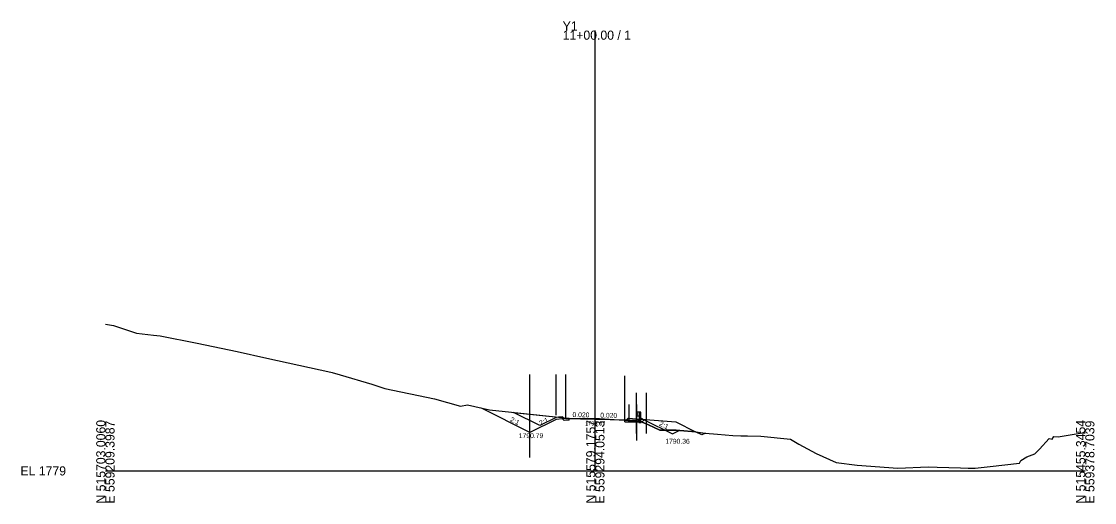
# Model space of a CAD drawing. Extents: x -26 to 303, y 990 to 1587.
# Drawn here: x -25.7 to 302.8, y 990.3 to 1137.7 of the extents above; entities that cross this region are included whole.
import ezdxf

# ---------------------------------------------------------------- set-up
doc = ezdxf.new("R2010")
doc.units = 0
for name, color, linetype in [('Exist Cross Section Cell', 7, 'Continuous'), ('Exist XS Center Line Elevation Label', 7, 'Continuous'), ('Exist XS Ground Line', 7, 'Continuous'), ('Prop XS Ditch Slope Text', 7, 'Continuous'), ('Prop XS Ditch Standard Text', 7, 'Continuous'), ('Prop XS Dump Level', 7, 'Continuous'), ('Prop XS Earthwork Shape', 7, 'Continuous'), ('Prop XS EOT Tick Mark', 7, 'Continuous'), ('Prop XS Finish Grade', 7, 'Continuous'), ('Prop XS Finish Grade Earthwork', 7, 'Continuous'), ('Prop XS Finish Grade Paved Shoulder', 7, 'Continuous'), ('Prop XS Finish Grade Pavement', 7, 'Continuous'), ('Prop XS Guardrail', 7, 'Continuous'), ('Prop XS Pvmt Edge Slope', 7, 'Continuous'), ('Prop XS SE Text', 7, 'Continuous'), ('Prop XS Side Slope Text', 7, 'Continuous'), ('Prop XS Subgrade Earthwork', 7, 'Continuous'), ('Scratch_Level_3', 7, 'Continuous'), ('Scratch_Level_6', 7, 'Continuous'), ('Typical Curb CELL', 7, 'Continuous')]:
    doc.layers.add(name, color=color, linetype=linetype)

msp = doc.modelspace()

# ---------------------------------------------------------------- linework, layer by layer
at = {"layer": 'Exist Cross Section Cell'}
for p, q in [((150, 1000), (150, 1134.87)), ((0, 1000), (150, 1000)), ((150, 1000), (300, 1000))]:
    msp.add_line(p, q, dxfattribs=at)
at = {"layer": 'Exist XS Ground Line'}
msp.add_lwpolyline([(0, 1044.96), (2.53, 1044.49), (9.5, 1042.18), (14.72, 1041.61), (16.82, 1041.37), (28.06, 1039.14), (40.38, 1036.55), (49.47, 1034.58), (69.05, 1030.26), (69.42, 1030.15), (71.85, 1029.42), (81.56, 1026.55), (85.51, 1025.2), (100.78, 1022.12), (108.77, 1019.8), (110.82, 1020.22), (117.62, 1018.66), (139.76, 1016.31), (141.98, 1016.08), (142.48, 1016.08), (150, 1016.07), (151.32, 1016.07), (157.33, 1015.64), (159.27, 1015.55), (163.39, 1015.04), (164.33, 1014.93), (166.3, 1014.11), (169.72, 1012.52), (172, 1012.5), (173.61, 1012.5), (174.74, 1012.49), (175.87, 1012.35), (180.8, 1011.97), (183.6, 1011.58), (187.44, 1011.21), (192.11, 1010.89), (194.5, 1010.73), (194.94, 1010.73), (195.79, 1010.75), (196.57, 1010.75), (200.72, 1010.63), (209.71, 1009.7), (212.32, 1008.2), (217.66, 1005.33), (223.77, 1002.53), (230.12, 1001.71), (242.62, 1000.87), (251.93, 1001.25), (254.66, 1001.1), (261.78, 1000.93), (264.17, 1000.83), (266.29, 1000.83), (270.87, 1001.32), (279.84, 1002.33), (280.32, 1003.21), (282.13, 1004.29), (284.6, 1005.28), (285.98, 1006.66), (288.94, 1009.91), (289.86, 1009.68), (290.38, 1010.49), (291.75, 1010.46), (299.07, 1011.62), (300, 1011.62)], dxfattribs=at)
msp.add_lwpolyline([(0, 1044.96), (2.53, 1044.49), (9.5, 1042.18), (14.72, 1041.61), (16.82, 1041.37), (28.06, 1039.14), (40.38, 1036.55), (49.47, 1034.58), (69.05, 1030.26), (69.42, 1030.15), (71.85, 1029.42), (81.56, 1026.55), (85.51, 1025.2), (100.78, 1022.12), (108.77, 1019.8), (110.82, 1020.22), (117.62, 1018.66), (139.76, 1016.31), (141.98, 1016.08), (142.48, 1016.08), (150, 1016.07), (151.32, 1016.07), (157.33, 1015.64), (159.27, 1015.55), (163.39, 1015.04), (164.33, 1014.93), (166.3, 1014.11), (169.72, 1012.52), (172, 1012.5), (173.61, 1012.5), (174.74, 1012.49), (175.87, 1012.35), (180.8, 1011.97), (183.6, 1011.58), (187.44, 1011.21), (192.11, 1010.89), (194.5, 1010.73), (194.94, 1010.73), (195.79, 1010.75), (196.57, 1010.75), (200.72, 1010.63), (209.71, 1009.7), (212.32, 1008.2), (217.66, 1005.33), (223.77, 1002.53), (230.12, 1001.71), (242.62, 1000.87), (251.93, 1001.25), (254.66, 1001.1), (261.78, 1000.93), (264.17, 1000.83), (266.29, 1000.83), (270.87, 1001.32), (279.84, 1002.33), (280.32, 1003.21), (282.13, 1004.29), (284.6, 1005.28), (285.98, 1006.66), (288.94, 1009.91), (289.86, 1009.68), (290.38, 1010.49), (291.75, 1010.46), (299.07, 1011.62), (300, 1011.62)], dxfattribs=at)
at = {"layer": 'Prop XS Dump Level'}
for p, q in [((141, 1016.03), (150, 1015.85)), ((150, 1015.85), (159, 1015.67))]:
    msp.add_line(p, q, dxfattribs=at)
at = {"layer": 'Prop XS Earthwork Shape'}
for points in [[(133, 1013.87), (124.98, 1017.88), (138.69, 1016.43), (138, 1016.37)], [(139.76, 1016.31), (140.24, 1016.26), (139.98, 1016.53), (138.69, 1016.43)], [(140.45, 1016.06), (140.24, 1016.26), (141.97, 1016.09)], [(159, 1015.66), (159.53, 1015.68), (160.02, 1016.17), (174.6, 1015), (180.65, 1011.98), (175.87, 1012.35), (174.74, 1012.49), (173.61, 1012.5), (172, 1012.5), (169.72, 1012.52), (166.3, 1014.11), (164.33, 1014.93), (163.39, 1015.04), (159.27, 1015.55), (159, 1015.56)], [(183.6, 1011.58), (183.73, 1011.56), (182.6, 1011), (180.65, 1011.98), (180.8, 1011.97)]]:
    msp.add_lwpolyline(points, close=True, dxfattribs=at)
at = {"layer": 'Prop XS EOT Tick Mark'}
for p, q in [((141, 1016.03), (141, 1017.03)), ((159, 1015.67), (159, 1016.67))]:
    msp.add_line(p, q, dxfattribs=at)
at = {"layer": 'Prop XS Finish Grade'}
for p, q in [((141, 1016.03), (139.97, 1015.95)), ((141, 1016.03), (139.98, 1015.95)), ((162.64, 1015.51), (164.01, 1016.17)), ((163.32, 1015.17), (164.2, 1015.14)), ((164.01, 1016.17), (165, 1015.68))]:
    msp.add_line(p, q, dxfattribs=at)
at = {"layer": 'Prop XS Finish Grade Earthwork'}
for p, q in [((130, 1011.79), (115.11, 1019.23)), ((138, 1015.79), (130, 1011.79)), ((139.97, 1015.95), (138, 1015.79)), ((165, 1015.68), (173.64, 1011.36)), ((173.64, 1011.36), (175.67, 1012.37))]:
    msp.add_line(p, q, dxfattribs=at)
at = {"layer": 'Prop XS Finish Grade Paved Shoulder'}
msp.add_line((159, 1015.67), (160.31, 1015.64), dxfattribs=at)
at = {"layer": 'Prop XS Finish Grade Pavement'}
for p, q in [((141, 1016.03), (150, 1015.85)), ((150, 1015.85), (159, 1015.67))]:
    msp.add_line(p, q, dxfattribs=at)
at = {"layer": 'Prop XS Guardrail'}
for p, q in [((162.67, 1017.77), (162.64, 1017.71)), ((162.64, 1017.71), (162.67, 1017.65)), ((162.67, 1017.16), (162.64, 1017.1)), ((162.64, 1017.1), (162.67, 1017.04)), ((162.96, 1017.97), (162.67, 1017.77)), ((162.67, 1017.65), (162.96, 1017.45)), ((162.96, 1017.36), (162.67, 1017.16)), ((162.67, 1017.04), (162.96, 1016.84)), ((163.46, 1017.97), (162.96, 1017.97)), ((162.96, 1017.45), (162.96, 1017.36)), ((162.96, 1016.84), (163.46, 1016.84)), ((163.46, 1017.97), (163.46, 1015.32)), ((163.96, 1017.97), (163.46, 1017.97)), ((163.46, 1015.29), (163.46, 1014.59)), ((163.96, 1015.32), (163.96, 1017.97)), ((163.96, 1014.59), (163.96, 1015.3))]:
    msp.add_line(p, q, dxfattribs=at)
at = {"layer": 'Prop XS Pvmt Edge Slope'}
msp.add_line((164.2, 1015.14), (164.33, 1015.01), dxfattribs=at)
at = {"layer": 'Prop XS Subgrade Earthwork'}
for p, q in [((140.45, 1015.48), (139.98, 1015.95)), ((141.97, 1015.51), (140.45, 1015.48)), ((141.97, 1015.51), (141.97, 1016.01)), ((159, 1015.08), (159, 1015.56)), ((164.33, 1015.01), (165, 1015.68)), ((159, 1015.08), (164.33, 1015.01))]:
    msp.add_line(p, q, dxfattribs=at)
at = {"layer": 'Scratch_Level_3'}
for p, q in [((160.31, 1020.31), (160.31, 1015.64)), ((162.64, 1020.31), (162.64, 1009.27))]:
    msp.add_line(p, q, dxfattribs=at)
at = {"layer": 'Scratch_Level_6'}
for p, q in [((130, 1004.09), (130, 1029.52)), ((138, 1017.03), (138, 1029.52)), ((141, 1017.03), (141, 1029.52)), ((159, 1016.67), (159, 1029.16)), ((162.64, 1011.47), (162.64, 1023.96)), ((165.64, 1011.47), (165.64, 1023.96))]:
    msp.add_line(p, q, dxfattribs=at)
at = {"layer": 'Typical Curb CELL'}
for p, q in [((160.3, 1015.23), (160.31, 1015.63)), ((163.32, 1015.17), (160.3, 1015.23)), ((160.31, 1015.64), (160.31, 1015.64)), ((160.32, 1015.64), (162.64, 1015.51)), ((160.54, 1015.37), (160.63, 1015.49)), ((160.66, 1015.38), (160.54, 1015.37)), ((160.63, 1015.49), (160.66, 1015.38)), ((161.3, 1015.31), (161.37, 1015.42)), ((161.47, 1015.34), (161.3, 1015.31)), ((161.37, 1015.42), (161.47, 1015.34)), ((161.79, 1015.35), (161.88, 1015.47)), ((161.91, 1015.35), (161.79, 1015.35)), ((161.88, 1015.47), (161.91, 1015.35)), ((162.55, 1015.28), (162.62, 1015.4)), ((162.72, 1015.32), (162.55, 1015.28)), ((162.62, 1015.4), (162.72, 1015.32)), ((162.64, 1015.51), (163.33, 1015.84)), ((163.13, 1015.51), (163.15, 1015.42)), ((163.29, 1015.47), (163.13, 1015.51)), ((163.15, 1015.42), (163.29, 1015.47)), ((163.32, 1015.17), (163.33, 1015.84))]:
    msp.add_line(p, q, dxfattribs=at)
for centre in [(160.39, 1015.46), (160.43, 1015.59), (160.8, 1015.51), (160.85, 1015.33), (160.91, 1015.29), (160.95, 1015.42), (161.02, 1015.41), (161.07, 1015.44), (161.12, 1015.33), (161.31, 1015.36), (161.52, 1015.34), (161.53, 1015.39), (161.55, 1015.45), (161.6, 1015.31), (161.7, 1015.35), (161.79, 1015.36), (161.91, 1015.31), (162.1, 1015.3), (162.16, 1015.27), (162.19, 1015.39), (162.32, 1015.42), (162.36, 1015.3), (162.56, 1015.34), (162.59, 1015.24), (162.76, 1015.32), (162.78, 1015.37), (163.04, 1015.33), (163.16, 1015.28), (163.26, 1015.55)]:
    msp.add_circle(centre, 0.00802, dxfattribs=at)
msp.add_arc((160.32, 1015.63), 0.0104, 86.8062, 178.8542, dxfattribs=at)

# ---------------------------------------------------------------- texts
at = {"layer": 'Exist Cross Section Cell'}
for s, p in [('Y1', (140, 1134.87)), ('11+00.00 / 1', (140, 1132.07)), ('EL 1779', (-26, 998.6))]:
    msp.add_text(s, height=2.8, dxfattribs=at).set_placement(p)
for s, p in [('N 515703.0060', (0, 990)), ('E 559209.3987', (2.8, 990)), ('N 515579.1757', (150, 990)), ('E 559294.0513', (152.8, 990)), ('N 515455.3454', (300, 990)), ('E 559378.7039', (302.8, 990))]:
    msp.add_text(s, height=2.8, rotation=90, dxfattribs=at).set_placement(p)
at = {"layer": 'Exist XS Center Line Elevation Label'}
msp.add_text('1795.07', height=1.25, dxfattribs=at).set_placement((146.84, 1013.91))
at = {"layer": 'Prop XS Ditch Slope Text'}
for rotation, p in [(333.4349, (123.74, 1015.25)), (26.5651, (133.28, 1013.84))]:
    msp.add_text('2:1', height=1.5, rotation=rotation, dxfattribs=at).set_placement(p)
at = {"layer": 'Prop XS Ditch Standard Text'}
for s, p in [('1790.79', (126.57, 1010.04)), ('1790.36', (171.43, 1008.33))]:
    msp.add_text(s, height=1.5, dxfattribs=at).set_placement(p)
at = {"layer": 'Prop XS SE Text'}
for p in [(143, 1016.5), (151.5, 1016.33)]:
    msp.add_text('0.020', height=1.5, rotation=358.8542, dxfattribs=at).set_placement(p)
at = {"layer": 'Prop XS Side Slope Text'}
msp.add_text('2:1', height=1.5, rotation=333.4349, dxfattribs=at).set_placement((169.4, 1013.97))

doc.saveas('drawing.dxf')
